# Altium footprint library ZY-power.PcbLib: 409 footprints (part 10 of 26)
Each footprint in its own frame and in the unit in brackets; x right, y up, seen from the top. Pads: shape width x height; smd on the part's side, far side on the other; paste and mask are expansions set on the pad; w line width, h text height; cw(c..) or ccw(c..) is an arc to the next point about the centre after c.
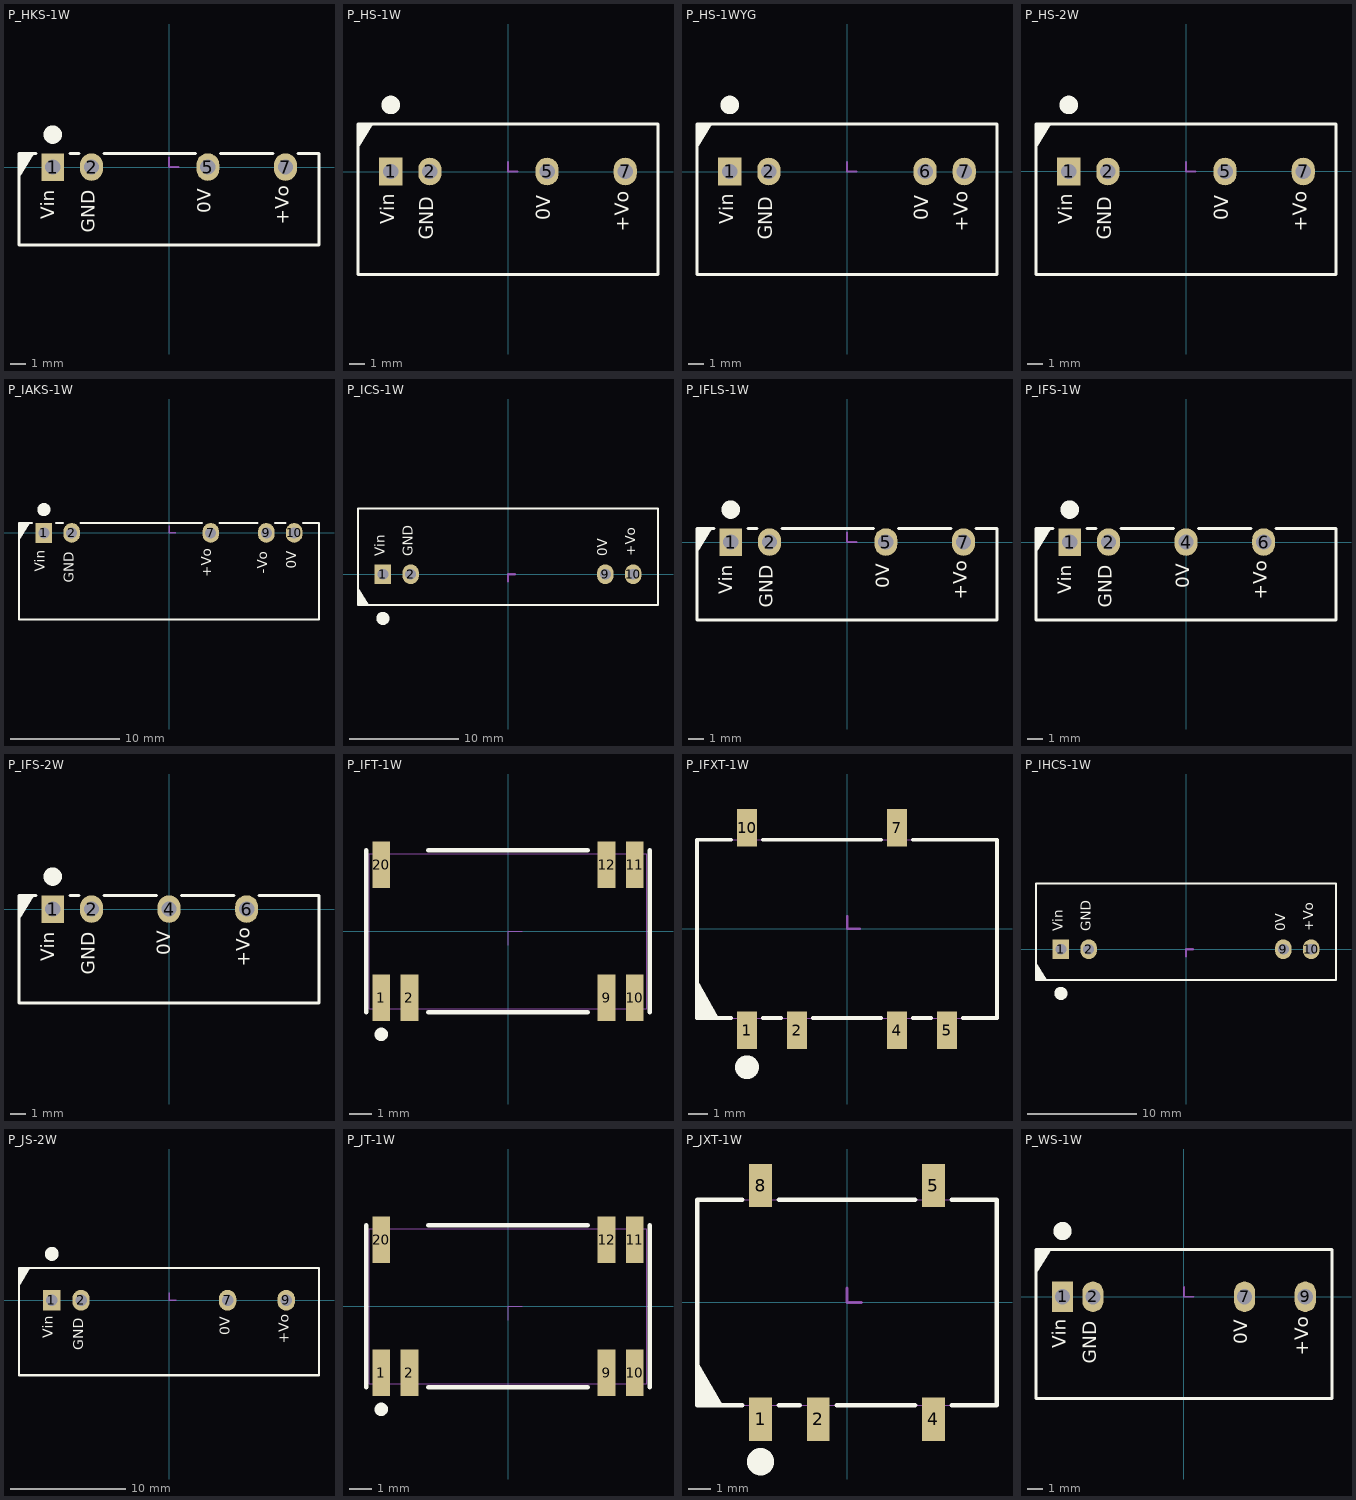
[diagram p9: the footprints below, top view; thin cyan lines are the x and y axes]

## P_HKS-1W [mm]
height 10.16
pads (4):
  rect 1.5x1.8 hole 1: 1(-7.62,0)
  oval 1.5x1.8 hole 1: 2(-5.08,0) 5(2.54,0) 7(7.62,0)
Top Overlay:
  circle w1: c-7.62,2.125 r0.1
  region: -9.83,-0.686 -9.83,0.9 -8.836,0.9
  lines w0.2: -8.72,0.9 -9.83,0.9 -9.83,-5.1 9.82,-5.1 9.82,0.9 8.44,0.9 ; -6.5,0.9 -5.9,0.9 ; -4.26,0.9 1.72,0.9 ; 3.36,0.9 6.8,0.9
  text "Vin" at -7.239,-3.435 h1.52
  text "GND" at -4.572,-4.318 h1.52
  text "0V" at 3.021,-3.036 h1.52
  text "+Vo" at 8.128,-3.776 h1.52
Mechanical 15:
  lines w0.127: 0,0.635 0,0 0.635,0
3D body "zhenjao01.stp": height 8.36, standoff -4.08, extent -8.32,-1.48 -6.92,0.12
3D body "zhenjao01.stp": height 8.36, standoff -4.08, extent -5.78,-1.48 -4.38,0.12
3D body "zhenjao01.stp": height 8.36, standoff -4.08, extent 1.84,-1.48 3.24,0.12
3D body "zhenjao01.stp": height 8.36, standoff -4.08, extent 6.92,-1.48 8.32,0.12
3D body: height 10.16, standoff 0, extent -9.83,-5.1 9.82,0.9

## P_HS-1W [mm]
height 12.5
pads (4):
  rect 1.5x1.8 hole 1: 1(-7.62,0)
  oval 1.5x1.8 hole 1: 2(-5.08,0) 5(2.54,0) 7(7.62,0)
Top Overlay:
  circle w1: c-7.62,4.325 r0.1
  region: -9.75,1.504 -9.75,3.1 -8.75,3.1
  lines w0.2: -9.75,-6.7 9.75,-6.7 9.75,3.1 -9.75,3.1 -9.75,-6.7
  text "+Vo" at 8.128,-3.903 h1.52
  text "0V" at 3.048,-3.163 h1.52
  text "GND" at -4.572,-4.445 h1.52
  text "Vin" at -7.112,-3.435 h1.52
Mechanical 15:
  lines w0.127: 0,0.635 0,0 0.635,0
3D body: height 12.5, standoff 0, extent -9.75,-6.7 9.75,3.1
3D body "zhenjao01.stp": height 8.36, standoff -4.08, extent 6.92,-1.48 8.32,0.12
3D body "zhenjao01.stp": height 8.36, standoff -4.08, extent 1.84,-1.48 3.24,0.12
3D body "zhenjao01.stp": height 8.36, standoff -4.08, extent -5.78,-1.48 -4.38,0.12
3D body "zhenjao01.stp": height 8.36, standoff -4.08, extent -8.32,-1.48 -6.92,0.12

## P_HS-1WYG [mm]
height 12.5
pads (4):
  rect 1.5x1.8 hole 1: 1(-7.62,0)
  oval 1.5x1.8 hole 1: 2(-5.08,0) 6(5.08,0) 7(7.62,0)
Top Overlay:
  circle w1: c-7.62,4.325 r0.1
  region: -9.75,1.504 -9.75,3.1 -8.75,3.1
  lines w0.2: -9.75,-6.7 9.75,-6.7 9.75,3.1 -9.75,3.1 -9.75,-6.7
  text "+Vo" at 8.128,-3.903 h1.52
  text "0V" at 5.588,-3.163 h1.52
  text "GND" at -4.572,-4.445 h1.52
  text "Vin" at -7.112,-3.435 h1.52
Mechanical 15:
  lines w0.127: 0,0.635 0,0 0.635,0
3D body: height 12.5, standoff 0, extent -9.75,-6.7 9.75,3.1
3D body "zhenjao01.stp": height 8.36, standoff -4.08, extent 6.92,-1.48 8.32,0.12
3D body "zhenjao01.stp": height 8.36, standoff -4.08, extent 4.38,-1.48 5.78,0.12
3D body "zhenjao01.stp": height 8.36, standoff -4.08, extent -5.78,-1.48 -4.38,0.12
3D body "zhenjao01.stp": height 8.36, standoff -4.08, extent -8.32,-1.48 -6.92,0.12

## P_HS-2W [mm]
height 12.5
pads (4):
  rect 1.5x1.8 hole 1: 1(-7.62,0)
  oval 1.5x1.8 hole 1: 2(-5.08,0) 5(2.54,0) 7(7.62,0)
Top Overlay:
  circle w1: c-7.62,4.325 r0.1
  region: -9.75,1.514 -9.75,3.1 -8.756,3.1
  lines w0.2: -9.75,-6.7 -9.75,3.1 9.75,3.1 9.75,-6.7 -9.75,-6.7
  text "+Vo" at 8.128,-3.903 h1.52
  text "0V" at 3.048,-3.163 h1.52
  text "GND" at -4.572,-4.445 h1.52
  text "Vin" at -7.112,-3.435 h1.52
Mechanical 15:
  lines w0.127: 0,0.635 0,0 0.635,0
3D body: height 12.5, standoff 0, extent -9.75,-6.7 9.75,3.1
3D body "zhenjao01.stp": height 8.36, standoff -4.08, extent 6.92,-1.48 8.32,0.12
3D body "zhenjao01.stp": height 8.36, standoff -4.08, extent 1.84,-1.48 3.24,0.12
3D body "zhenjao01.stp": height 8.36, standoff -4.08, extent -5.78,-1.48 -4.38,0.12
3D body "zhenjao01.stp": height 8.36, standoff -4.08, extent -8.32,-1.48 -6.92,0.12

## P_IAKS-1W [mm]
height 11.4
pads (5):
  rect 1.5x1.8 hole 1: 1(-11.43,0)
  oval 1.5x1.8 hole 1: 2(-8.89,0) 7(3.81,0) 9(8.89,0) 10(11.43,0)
Top Overlay:
  circle w1: c-11.43,2.125 r0.1
  region: -13.7,-0.686 -13.7,0.9 -12.706,0.9
  lines w0.2: -12.53,0.9 -13.7,0.9 -13.7,-7.9 13.7,-7.9 13.7,0.9 12.25,0.9 ; -10.31,0.9 -9.71,0.9 ; -8.07,0.9 2.99,0.9 ; 4.63,0.9 8.07,0.9 ; 9.71,0.9 10.61,0.9
  text "Vin" at -11.049,-3.562 h1.52
  text "GND" at -8.382,-4.572 h1.52
  text "+Vo" at 4.191,-4.03 h1.52
  text "-Vo" at 9.271,-3.718 h1.52
  text "0V" at 11.938,-3.29 h1.52
Mechanical 15:
  lines w0.127: 0,0.635 0,0 0.635,0
3D body "zhenjao01.stp": height 8.36, standoff -4.08, extent -12.13,-1.48 -10.73,0.12
3D body: height 10.1, standoff 0, extent -13.7,-7.9 13.7,0.9
3D body "zhenjao01.stp": height 8.36, standoff -4.08, extent -9.59,-1.48 -8.19,0.12
3D body "zhenjao01.stp": height 8.36, standoff -4.08, extent 3.11,-1.48 4.51,0.12
3D body "zhenjao01.stp": height 8.36, standoff -4.08, extent 8.19,-1.48 9.59,0.12
3D body "zhenjao01.stp": height 8.36, standoff -4.08, extent 10.73,-1.48 12.13,0.12

## P_ICS-1W [mm]
height 11.5
pads (4):
  rect 1.5x1.8 hole 1: 1(-11.43,0)
  oval 1.5x1.8 hole 1: 2(-8.89,0) 9(8.89,0) 10(11.43,0)
Top Overlay:
  circle w1: c-11.43,-4.025 r0.1
  region: -13.7,-1.214 -13.7,-2.8 -12.706,-2.8
  lines w0.2: -13.7,-2.8 13.7,-2.8 13.7,6 -13.7,6 -13.7,-2.8
  text "Vin" at -10.935,1.626 h1.52
  text "GND" at -8.395,1.625 h1.52
  text "0V" at 9.385,1.625 h1.52
  text "+Vo" at 11.925,1.625 h1.52
Mechanical 15:
  lines w0.203: 0,-0.635 0,0 0.635,0
3D body: height 10.1, standoff 0, extent -13.7,-2.8 13.7,6
3D body "zhenjao01.stp": height 8.36, standoff -4.08, extent 10.73,-0.12 12.13,1.48
3D body "zhenjao01.stp": height 8.36, standoff -4.08, extent 8.19,-0.12 9.59,1.48
3D body "zhenjao01.stp": height 8.36, standoff -4.08, extent -12.13,-0.12 -10.73,1.48
3D body "zhenjao01.stp": height 8.36, standoff -4.08, extent -9.59,-0.12 -8.19,1.48

## P_IFLS-1W [mm]
height 10.16
pads (4):
  rect 1.5x1.8 hole 1: 1(-7.62,0)
  oval 1.5x1.8 hole 1: 2(-5.08,0) 5(2.54,0) 7(7.62,0)
Top Overlay:
  circle w1: c-7.62,2.125 r0.1
  region: -9.83,-0.686 -9.83,0.9 -8.836,0.9
  lines w0.2: -8.72,0.9 -9.83,0.9 -9.83,-5.1 9.82,-5.1 9.82,0.9 8.44,0.9 ; -6.5,0.9 -5.9,0.9 ; -4.26,0.9 1.72,0.9 ; 3.36,0.9 6.8,0.9
  text "0V" at 3.048,-3.037 h1.52
  text "Vin" at -7.239,-3.435 h1.52
  text "GND" at -4.572,-4.318 h1.52
  text "+Vo" at 8.128,-3.776 h1.52
Mechanical 15:
  lines w0.127: 0,0.635 0,0 0.635,0
3D body "zhenjao01.stp": height 8.36, standoff -4.08, extent -8.32,-1.48 -6.92,0.12
3D body "zhenjao01.stp": height 8.36, standoff -4.08, extent -5.78,-1.48 -4.38,0.12
3D body "zhenjao01.stp": height 8.36, standoff -4.08, extent 1.84,-1.48 3.24,0.12
3D body "zhenjao01.stp": height 8.36, standoff -4.08, extent 6.92,-1.48 8.32,0.12
3D body: height 10.16, standoff 0, extent -9.83,-5.1 9.77,0.9

## P_IFS-1W [mm]
height 10.16
pads (4):
  rect 1.5x1.8 hole 1: 1(-7.62,0)
  oval 1.5x1.8 hole 1: 2(-5.08,0) 4(0,0) 6(5.08,0)
Top Overlay:
  circle w1: c-7.62,2.125 r0.1
  region: -9.83,-0.686 -9.83,0.9 -8.836,0.9
  lines w0.2: -8.72,0.9 -9.83,0.9 -9.83,-5.1 9.82,-5.1 9.82,0.9 5.9,0.9 ; -6.5,0.9 -5.9,0.9 ; -4.26,0.9 -0.82,0.9 ; 0.82,0.9 4.26,0.9
  text "Vin" at -7.239,-3.435 h1.52
  text "GND" at -4.572,-4.318 h1.52
  text "+Vo" at 5.588,-3.776 h1.52
  text "0V" at 0.508,-3.037 h1.52
Mechanical 15:
  lines w0.127: 0,0.635 0,0 0.635,0
3D body "zhenjao01.stp": height 8.36, standoff -4.08, extent -8.32,-1.48 -6.92,0.12
3D body "zhenjao01.stp": height 8.36, standoff -4.08, extent -5.78,-1.48 -4.38,0.12
3D body "zhenjao01.stp": height 8.36, standoff -4.08, extent -0.7,-1.48 0.7,0.12
3D body "zhenjao01.stp": height 8.36, standoff -4.08, extent 4.38,-1.48 5.78,0.12
3D body: height 10.16, standoff 0, extent -9.83,-5.1 9.77,0.9

## P_IFS-2W [mm]
height 10.16
pads (4):
  rect 1.5x1.8 hole 1: 1(-7.62,0)
  oval 1.5x1.8 hole 1: 2(-5.08,0) 4(0,0) 6(5.08,0)
Top Overlay:
  circle w1: c-7.62,2.125 r0.1
  region: -9.83,-0.686 -9.83,0.9 -8.836,0.9
  lines w0.2: -8.72,0.9 -9.83,0.9 -9.83,-6.15 9.82,-6.15 9.82,0.9 5.9,0.9 ; -6.5,0.9 -5.9,0.9 ; -4.26,0.9 -0.82,0.9 ; 0.82,0.9 4.26,0.9
  text "Vin" at -7.239,-3.435 h1.52
  text "GND" at -4.572,-4.318 h1.52
  text "0V" at 0.381,-3.036 h1.52
  text "+Vo" at 5.588,-3.776 h1.52
Mechanical 15:
  lines w0.127: 0,0.635 0,0 0.635,0
3D body "zhenjao01.stp": height 8.36, standoff -4.08, extent -8.32,-1.48 -6.92,0.12
3D body "zhenjao01.stp": height 8.36, standoff -4.08, extent -5.78,-1.48 -4.38,0.12
3D body "zhenjao01.stp": height 8.36, standoff -4.08, extent -0.7,-1.48 0.7,0.12
3D body "zhenjao01.stp": height 8.36, standoff -4.08, extent 4.38,-1.48 5.78,0.12
3D body: height 10.16, standoff 0, extent -9.83,-6.15 9.77,0.9

## P_IFT-1W [mm]
height 3
pads (7):
  rect 0.8x2.1 smd: 1(-5.715,-3) 2(-4.445,-3) 9(4.445,-3) 10(5.715,-3) 11(5.715,3) 12(4.445,3) 20(-5.715,3)
Top Overlay:
  circle w0.4: c-5.715,-4.649 r0.1
  lines w0.2: -6.4,-3.65 -6.4,3.65 ; -3.6,-3.65 3.6,-3.65 ; -3.6,3.65 3.6,3.65 ; 6.4,-3.65 6.4,3.65
Mechanical 13:
  lines w0.05: -6.25,-3.5 6.25,-3.5 6.25,3.5 -6.25,3.5 -6.25,-3.5
Mechanical 15:
  lines w0.05: 0,-0.635 0,0 0.635,0

## P_IFXT-1W [mm]
height 7.25
pads (6):
  rect 1x1.9 smd: 1(-5.08,-5.15) 2(-2.54,-5.15) 4(2.54,-5.15) 5(5.08,-5.15) 7(2.54,5.15) 10(-5.08,5.15)
Top Overlay:
  circle w1: c-5.082,-7.023 r0.1
  region: -6.504,-4.53 -7.62,-2.591 -7.62,-4.53
  lines w0.2: -5.893,-4.53 -7.62,-4.53 -7.62,4.53 -5.893,4.53 ; -4.267,-4.53 -3.354,-4.53 ; -4.267,4.53 1.727,4.53 ; -1.726,-4.53 1.727,-4.53 ; 3.353,-4.53 4.266,-4.53 ; 3.353,4.53 7.62,4.53 7.62,-4.53 5.893,-4.53
Mechanical 15:
  lines w0.051: -7.62,-4.53 -7.62,4.53 7.62,4.53 7.62,-4.53 -7.62,-4.53
  lines w0.127: 0,0.635 0,0 0.635,0

## P_IHCS-1W [mm]
height 11.4
pads (4):
  rect 1.5x1.8 hole 1: 1(-11.43,0)
  oval 1.5x1.8 hole 1: 2(-8.89,0) 9(8.89,0) 10(11.43,0)
Top Overlay:
  circle w1: c-11.43,-4.025 r0.1
  region: -13.7,-1.214 -13.7,-2.8 -12.706,-2.8
  lines w0.2: -13.7,-2.8 13.7,-2.8 13.7,6 -13.7,6 -13.7,-2.8
  text "Vin" at -10.935,1.626 h1.52
  text "GND" at -8.395,1.625 h1.52
  text "0V" at 9.385,1.625 h1.52
  text "+Vo" at 11.925,1.625 h1.52
Mechanical 15:
  lines w0.203: 0,-0.635 0,0 0.635,0
3D body: height 10.1, standoff 0, extent -13.7,-2.8 13.7,6
3D body "zhenjao01.stp": height 8.36, standoff -4.08, extent 10.73,-0.12 12.13,1.48
3D body "zhenjao01.stp": height 8.36, standoff -4.08, extent 8.19,-0.12 9.59,1.48
3D body "zhenjao01.stp": height 8.36, standoff -4.08, extent -12.13,-0.12 -10.73,1.48
3D body "zhenjao01.stp": height 8.36, standoff -4.08, extent -9.59,-0.12 -8.19,1.48

## P_JS-2W [mm]
height 12.5
pads (4):
  rect 1.5x1.8 hole 1: 1(-10.16,0)
  oval 1.5x1.8 hole 1: 2(-7.62,0) 7(5.08,0) 9(10.16,0)
Top Overlay:
  circle w1: c-10.16,4.025 r0.1
  region: -13,1.214 -13,2.8 -12.006,2.8
  lines w0.2: -13,-6.5 -13,2.8 13,2.8 13,-6.5 -13,-6.5
  text "GND" at -7.112,-4.321 h1.52
  text "Vin" at -9.779,-3.307 h1.52
  text "0V" at 5.568,-3.037 h1.52
  text "+Vo" at 10.668,-3.775 h1.52
Mechanical 15:
  lines w0.127: 0,0.635 0,0 0.635,0
3D body "zhenjao01.stp": height 8.36, standoff -4.08, extent -10.86,-1.48 -9.46,0.12
3D body: height 10.1, standoff 0, extent -13,-6.5 13,2.8
3D body "zhenjao01.stp": height 8.36, standoff -4.08, extent -8.32,-1.48 -6.92,0.12
3D body "zhenjao01.stp": height 8.36, standoff -4.08, extent 4.38,-1.48 5.78,0.12
3D body "zhenjao01.stp": height 8.36, standoff -4.08, extent 9.46,-1.48 10.86,0.12

## P_JT-1W [mm]
height 3
pads (7):
  rect 0.8x2.1 smd: 1(-5.715,-3) 2(-4.445,-3) 9(4.445,-3) 10(5.715,-3) 11(5.715,3) 12(4.445,3) 20(-5.715,3)
Top Overlay:
  circle w0.4: c-5.715,-4.649 r0.1
  lines w0.2: -6.4,-3.65 -6.4,3.65 ; -3.6,-3.65 3.6,-3.65 ; -3.6,3.65 3.6,3.65 ; 6.4,-3.65 6.4,3.65
Mechanical 13:
  lines w0.05: -6.25,-3.5 -6.25,3.5 6.25,3.5 6.25,-3.5 -6.25,-3.5
Mechanical 15:
  lines w0.05: 0,-0.635 0,0 0.635,0

## P_JXT-1W [mm]
height 7.25
pads (5):
  rect 1x1.9 smd: 1(-3.81,-5.15) 2(-1.27,-5.15) 4(3.81,-5.15) 5(3.81,5.15) 8(-3.81,5.15)
Top Overlay:
  circle w1: c-3.812,-7.023 r0.1
  region: -5.484,-4.53 -6.6,-2.591 -6.6,-4.53
  lines w0.2: -4.623,-4.53 -6.6,-4.53 -6.6,4.53 -4.623,4.53 ; -2.997,-4.53 -2.084,-4.53 ; -2.997,4.53 2.997,4.53 ; -0.456,-4.53 2.997,-4.53 ; 4.623,-4.53 6.6,-4.53 6.6,4.53 4.623,4.53
Mechanical 15:
  lines w0.051: -6.6,-4.53 -6.6,4.53 6.6,4.53 6.6,-4.53 -6.6,-4.53
  lines w0.127: 0,0.635 0,0 0.635,0

## P_WS-1W [mm]
height 12.5
pads (4):
  rect 1.4x2 hole 1: 1(-8,0)
  oval 1.4x2 hole 1: 2(-6,0) 7(4,0) 9(8,0)
Top Overlay:
  circle w1: c-8,4.325 r0.1
  region: -9.75,1.514 -9.75,3.1 -8.756,3.1
  lines w0.2: -9.75,-6.7 -9.75,3.1 9.75,3.1 9.75,-6.7 -9.75,-6.7
  text "+Vo" at 8.5,-3.875 h1.52
  text "0V" at 4.48,-3.137 h1.52
  text "GND" at -5.475,-4.421 h1.52
  text "Vin" at -7.492,-3.407 h1.52
Mechanical 15:
  lines w0.127: 0,0.635 0,0 0.635,0
3D body: height 12.5, standoff 0, extent -9.75,-6.7 9.75,3.1
3D body "zhenjao01.stp": height 8.36, standoff -4.08, extent -8.7,-1.48 -7.3,0.12
3D body "zhenjao01.stp": height 8.36, standoff -4.08, extent -6.7,-1.48 -5.3,0.12
3D body "zhenjao01.stp": height 8.36, standoff -4.08, extent 3.3,-1.48 4.7,0.12
3D body "zhenjao01.stp": height 8.36, standoff -4.08, extent 7.3,-1.48 8.7,0.12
